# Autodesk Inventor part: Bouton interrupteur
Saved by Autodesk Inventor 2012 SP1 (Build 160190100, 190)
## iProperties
Created: 2014-12
Part Number: Bouton interrupteur
Material: Default
Document SubType Name: Modeling
Designer: Bruno
Density: 1 g/cm^3
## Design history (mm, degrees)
node "Bouton interrupteur1"
node "Bouton interrupteur"
node "Base1"
